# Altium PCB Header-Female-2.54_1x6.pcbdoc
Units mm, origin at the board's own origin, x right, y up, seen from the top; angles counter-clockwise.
Board outline 28.5 x 15.26 mm, 2 copper layers (Top Layer, Bottom Layer), stack 0 mm thick; 1 components, 0 nets, 6 pads, 0 vias.
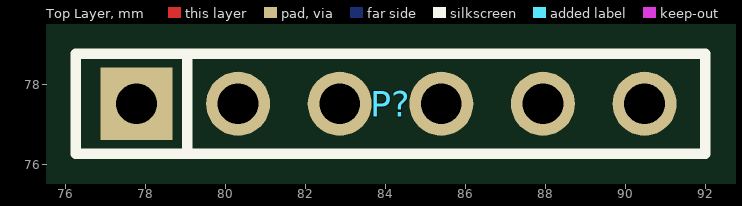
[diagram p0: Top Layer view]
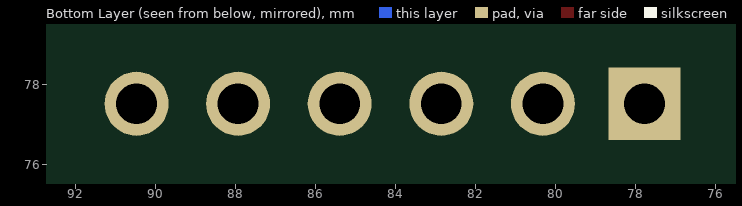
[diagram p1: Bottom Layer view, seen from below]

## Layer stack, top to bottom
Top Layer: signal copper (thickness not stored)
Bottom Layer: signal copper (thickness not stored)

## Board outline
98.349,69.85 69.85,69.85 69.85,85.11 98.349,85.11

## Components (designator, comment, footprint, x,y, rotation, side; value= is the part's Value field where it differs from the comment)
P? "2.54-1*6P母" HDR-TH_6P-P2.54-V-F 84.13,77.511 r0 top

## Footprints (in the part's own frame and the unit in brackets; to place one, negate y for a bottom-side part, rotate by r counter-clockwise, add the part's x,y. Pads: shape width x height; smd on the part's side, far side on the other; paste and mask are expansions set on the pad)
HDR-TH_6P-P2.54-V-F [mil]
  rect 70.9x70.9 hole 40.2: 1(-250,0)
  round 63 hole 40.2: 2(-150,0) 3(-50,0) 4(50,0) 5(150,0) 6(250,0)
  silkscreen extent -310,-49 310,49

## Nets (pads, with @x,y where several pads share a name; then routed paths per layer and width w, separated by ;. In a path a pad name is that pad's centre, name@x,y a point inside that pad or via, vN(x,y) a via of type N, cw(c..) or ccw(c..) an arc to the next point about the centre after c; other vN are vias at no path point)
pads on no net: P?.1 P?.2 P?.3 P?.4 P?.5 P?.6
